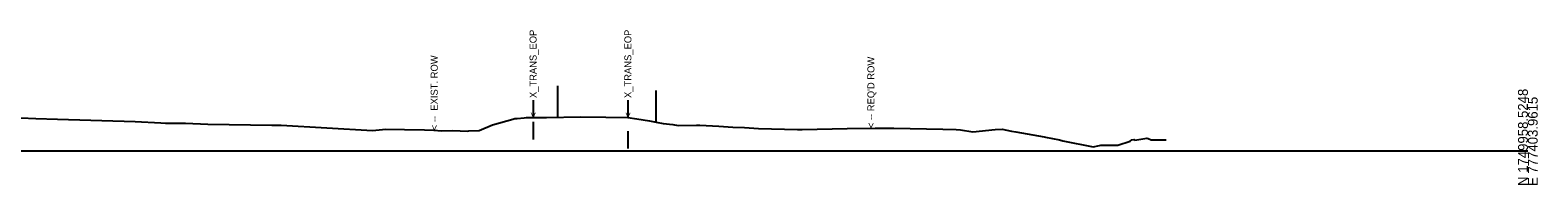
# Model space of a CAD drawing. Extents: x 776426 to 854588, y 1736205 to 1756790.
# Drawn here: x 805244.4 to 805673.6, y 1746705.1 to 1746749.1 of the extents above; entities that cross this region are included whole.
import ezdxf

# ---------------------------------------------------------------- set-up
doc = ezdxf.new("R2010")
doc.units = 0
for name, color, linetype in [('DTM CONTOURS_MAJOR_TX', 7, 'Continuous'), ('DTM_X_FLOW_ARROWS', 7, 'Continuous'), ('TRANS_EOP_PAVED', 7, 'Continuous'), ('X_TRANS_EOP', 7, 'Continuous'), ('XS_P_ROW', 7, 'Continuous'), ('XS_X_PAVEMENT', 7, 'Continuous'), ('XS_X_ROW', 7, 'Continuous')]:
    doc.layers.add(name, color=color, linetype=linetype)

msp = doc.modelspace()

# ---------------------------------------------------------------- linework, layer by layer
at = {"layer": 'DTM CONTOURS_MAJOR_TX'}
msp.add_line((805170.79, 1746714.76), (805670.79, 1746714.76), dxfattribs=at)
at = {"layer": 'DTM_X_FLOW_ARROWS'}
msp.add_lwpolyline([(805241.81, 1746724.14), (805246.01, 1746723.98), (805252.24, 1746723.81), (805274.3, 1746723.12), (805281.63, 1746722.7), (805282.98, 1746722.64), (805288.62, 1746722.63), (805294.98, 1746722.37), (805313.27, 1746722.08), (805315.89, 1746722.03), (805341.92, 1746720.58), (805345.69, 1746720.94), (805351.02, 1746720.85), (805356.69, 1746720.73), (805359.37, 1746720.64), (805361.55, 1746720.5), (805364.73, 1746720.51), (805368.96, 1746720.34), (805369.3, 1746720.43), (805372.3, 1746720.51), (805376.04, 1746722.18), (805381.82, 1746723.78), (805382.42, 1746723.94), (805383.04, 1746723.97), (805385.08, 1746724.16), (805385.66, 1746724.21), (805387.61, 1746724.22), (805391.4, 1746724.27), (805401.24, 1746724.44), (805408.3, 1746724.38), (805414.59, 1746724.24), (805417.15, 1746723.88), (805420.74, 1746723.33), (805422.68, 1746722.92), (805424.61, 1746722.57), (805427.41, 1746722.28), (805428.86, 1746721.96), (805434.1, 1746722.05), (805435.08, 1746722.07), (805440.48, 1746721.77), (805444.44, 1746721.51), (805447.79, 1746721.41), (805451.78, 1746721.15), (805462.89, 1746720.88), (805464.18, 1746720.88), (805477, 1746721.17), (805485.03, 1746721.23), (805486.41, 1746721.24), (805490.3, 1746721.22), (805504.25, 1746720.98), (805508.07, 1746720.87), (805509.29, 1746720.73), (805512.8, 1746720.18), (805519.11, 1746720.85), (805521.14, 1746720.93), (805523.77, 1746720.38), (805525.06, 1746720.15), (805533.07, 1746718.75), (805533.52, 1746718.68), (805537.48, 1746717.89), (805538.36, 1746717.59), (805547, 1746715.92), (805548.85, 1746716.28), (805549.21, 1746716.34), (805552.96, 1746716.4), (805554.03, 1746716.4), (805557.53, 1746717.5), (805558.09, 1746717.89), (805558.64, 1746717.95), (805558.95, 1746717.78), (805562.34, 1746718.35), (805562.74, 1746718.25), (805563.59, 1746717.92), (805566.8, 1746717.88), (805567.83, 1746717.89)], dxfattribs=at)
at = {"layer": 'TRANS_EOP_PAVED'}
for p, q in [((805394.52, 1746733.32), (805394.52, 1746724.32)), ((805394.52, 1746733.32), (805394.52, 1746724.32)), ((805422.58, 1746731.94), (805422.58, 1746722.94)), ((805422.58, 1746731.94), (805422.58, 1746722.94))]:
    msp.add_line(p, q, dxfattribs=at)
at = {"layer": 'X_TRANS_EOP'}
for p, q in [((805387.6, 1746729.22), (805387.6, 1746724.22)), ((805387.6, 1746729.22), (805387.6, 1746724.22)), ((805414.59, 1746729.24), (805414.59, 1746724.24)), ((805414.59, 1746729.24), (805414.59, 1746724.24)), ((805387.6, 1746722.98), (805387.6, 1746717.98)), ((805414.59, 1746720.41), (805414.59, 1746715.41))]:
    msp.add_line(p, q, dxfattribs=at)

# ---------------------------------------------------------------- texts
at = {"layer": 'DTM CONTOURS_MAJOR_TX'}
for s, p in [('N 1749958.5248', (805670.79, 1746704.76)), ('E 777403.9615', (805673.59, 1746704.76))]:
    msp.add_text(s, height=2.8, rotation=90, dxfattribs=at).set_placement(p)
at = {"layer": 'XS_P_ROW'}
msp.add_text("< -- REQ'D ROW", height=2, rotation=90, dxfattribs=at).set_placement((805484.77, 1746721.22))
at = {"layer": 'XS_X_PAVEMENT'}
for p in [(805388.6, 1746724.22), (805415.59, 1746724.24)]:
    msp.add_text('< --  X_TRANS_EOP', height=2, rotation=90, dxfattribs=at).set_placement(p)
at = {"layer": 'XS_X_ROW'}
msp.add_text('< --  EXIST. ROW', height=2, rotation=90, dxfattribs=at).set_placement((805360.46, 1746720.63))

doc.saveas('drawing.dxf')
